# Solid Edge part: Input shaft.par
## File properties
Author: Chalangana Oshan
Template: iso metric part.par
Last saved by: Nimesh.N
Revision: 41
Application: Solid Edge
Density: 7800.000 kg/m^3
Accuracy: 0.990
Username: Nimesh.N
Material: Steel - Free Cutting:1.0764 , 36SMn14
Face Style: Steel
Fill Style: ANSI32(Steel)
Grouping: Steel\Steel - Free Cutting ( Higher P or S content)
LibraryName: Materials-DIN
Coef. of Thermal Exp: 1.1e-05
Thermal Conductivity: 14.0
Specific Heat: 440.0
Modulus of Elasticity: 210000003072.0
Poisson's Ratio: 0.28
Yield Stress: 420000000.0
Ultimate Stress: 670000000.0
Elongation: 0.0
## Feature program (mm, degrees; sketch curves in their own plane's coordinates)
sketch for "unnamed Protrusion 1" plane through (0, 0, 0) normal (0, 0, 1) x-axis (1, 0, 0)
  circle centre (0, 0) radius 32.5
extrude "unnamed Protrusion 1" add finite 120 along +normal
chamfer "Chamfer_3" setback 3
sketch for "ExtrudedProtrusion_2" plane through (0, 0, 120) normal (0, 0, 1) x-axis (-1, 0, 0)
extrude "ExtrudedProtrusion_2" add finite 189 along +normal
sketch for "ExtrudedProtrusion_3" plane through (0, 0, 309) normal (0, 0, 1) x-axis (-1, 0, 0)
extrude "ExtrudedProtrusion_3" add finite 6 along +normal
chamfer "Chamfer_4" setback 3
sketch for "unnamed RevolvedCutout 1" plane through (0, 0, 0) normal (1, 0, 0) x-axis (0, 1, 0)
revolve "unnamed RevolvedCutout 1" cut full turn 360 deg
sketch for "ExtrudedCutout_5" plane through (0, 0, 223.5) normal (0, 0, -1) x-axis (0, 1, 0)
extrude "ExtrudedCutout_5" cut finite 40 along -normal
fillet "Round_1" radius 10
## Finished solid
Body 1: solid body, 22 faces, 36 edges, 16 vertices.
  Faces by surface: plane 11, cylinder 9, cone 2
  Edges by curve: circle 18, line 14, intersection 4
Bounding box of the edges (mm): 72.000 x 72.000 x 315.000, from (-36, -36, 0) to (36, 36, 315).
Cylindrical faces by radius (mm): R10 x4, R32.5 x2, R34 x2, R36 x1
Conical faces (half-angle, radius in mm at the cone's reference point): 45 deg R29.5 x1, 45 deg R36 x1
Planar faces by outward normal: +x 1, +y 1, +z 3, -y 1, -z 5
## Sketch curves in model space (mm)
line (0, -32.5, 175.85) -> (0, -32.5, 178.5)
line (0, -32.5, 178.5) -> (0, -34, 178.5)
line (0, -34, 178.5) -> (0, -34, 175.85)
line (0, -34, 175.85) -> (0, -32.5, 175.85)
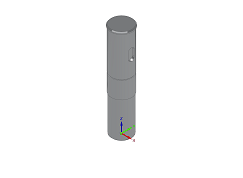
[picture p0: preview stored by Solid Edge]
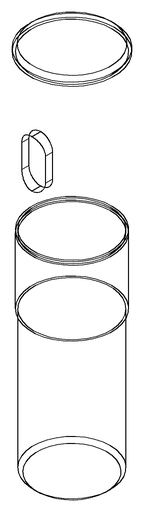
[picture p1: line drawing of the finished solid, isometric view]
